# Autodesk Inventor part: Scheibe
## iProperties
Created: 2007-11
Part Number: Scheibe
Document SubType Name: Modeling
Designer: Benno
Manufacturer: Standard
Standards Organization: Custom
Author: Benno
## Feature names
1. Extrusion1
